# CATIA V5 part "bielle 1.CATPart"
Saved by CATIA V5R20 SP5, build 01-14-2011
Part number: bielle 1
Property "epaisseurbielle1": 500 mm
Publications: "epaisseurbielle1"
Bounding box of the stored display mesh (mm): x -650 to 650, y -250 to 250, z -660 to 11132.604
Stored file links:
  M:\EU_thinkMotion\IAO_2010\iao\IAO_MMS_Groupe1\Problemes\gduval\Gduval\train d'aterrissage squelette + piece kinematic\bielle 1.CATPart
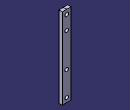
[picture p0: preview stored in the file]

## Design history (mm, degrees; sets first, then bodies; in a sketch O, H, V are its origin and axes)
Body1 (main body)
  Point1 to Point3: stored without definition
  Sketch1 on zx-plane, origin (0, 0, 0), H (-1, 0, 0), V (0, 0, 1)
    point P1 (650, 11132.604)
    line L1 (650, 11132.604) -> (0, 11132.604)
    line L2 (0, -660) -> (650, -660)
    line L3 (650, -660) -> (650, 11132.604)
    point P2 (0, 11132.604)
    point P3 (0, -660)
    point P4 (650, -660)
    axis line L4 (0, -1185.8182) -> (0, 12553.9509)
    point P5 (0, 12553.9509)
    reference projected point E1 (0, 0) from Point2
    reference projected point E2 (0, 0) from Point2
    reference projected point E3 (0, 10472.604) from Point3
    point P7 (-650, 11132.604)
    point P8 (-650, -660)
    line L5 (-650, -660) -> (-650, 11132.604)
    point P9 (0, 11132.604)
    line L6 (-650, 11132.604) -> (0, 11132.604)
    point P10 (0, -660)
    line L7 (0, -660) -> (-650, -660)
    distance L3 L4 = 650
    distance L2 E2 = 660
    distance L1 E3 = 660
    horizontal: L1 H, L2 H
    vertical: L3 V
    coincidence: P5 V, L4 E1, P3 L4, P2 L4, P2 P9, P3 P10
    symmetry: P1 P7 L4, P4 P8 L4, L3 L5 L4, P2 P9 L4, L1 L6 L4, P3 P10 L4, L2 L7 L4
  Pad1: profile Sketch1, direction (0, 1, 0), length 250, mirrored extent
  Point4: stored without definition
  Sketch2 on start face of Pad1, origin (165.5968, -250, 4527.5449), H (1, 0, 0), V (0, 0, 1)
    point P1 (-165.5968, 5945.0591)
    reference projected point E1 (-165.5968, 5945.0591) from Point1
    coincidence: P1 E1
  Hole1: placed by Sketch2, at (0, -250, 10472.604) direction (0, 1, 0), diameter 520, through (limit type 6)
  Point5: stored without definition
  Sketch3 on start face of Pad1, origin (0, -250, 3519.877), H (1, 0, 0), V (0, 0, 1)
    point P1 (0, 0)
    reference projected point E1 (0, 0) from Point4
    coincidence: E1 P1
  Hole2: placed by Sketch3, at (0, -250, 3519.877) direction (0, 1, 0), diameter 520, through (limit type 6)
  Sketch4 on start face of Pad1, origin (0, -250, 8460.769), H (1, 0, 0), V (0, 0, 1)
    point P1 (0, 0)
    reference projected point E1 (0, 0) from Point5
    coincidence: E1 P1
  Hole3: placed by Sketch4, at (0, -250, 8460.769) direction (0, 1, 0), diameter 520, through (limit type 6)
  Sketch5 on start face of Pad1, origin (0, -250, 0), H (1, 0, 0), V (0, 0, 1)
    point P1 (0, 0)
    reference projected point E1 (0, 0) from Point2
    coincidence: E1 P1
  Hole4: placed by Sketch5, at (0, -250, 0) direction (0, 1, 0), diameter 520, through (limit type 6)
